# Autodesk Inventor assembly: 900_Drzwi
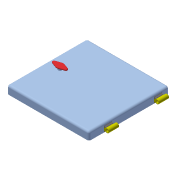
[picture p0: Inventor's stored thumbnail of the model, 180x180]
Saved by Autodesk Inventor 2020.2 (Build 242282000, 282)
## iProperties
Created: 2006-01
Part Number: 900_Drzwi
Document SubType Name: Weldment
Designer: F.Stasiak
Weld Material: Spawane aluminium-6061
Manager: www.cadconsulting.pl
Company: Fabian Stasiak CAD Consulting
Author: F.Stasiak
Subject: Zbiór ćwiczeń. Autodesk Inventor 2020. Kurs podstawowy
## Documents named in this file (5)
- C:\2020_Kurs_podstawowy\R7 Prezentacje\Komponenty\900_Drzwi.iam
- C:\2020_Kurs_podstawowy\R7 Prezentacje\Komponenty\900_Pokrywa.ipt
- C:\2020_Kurs_podstawowy\R7 Prezentacje\Komponenty\900_Zawias1.ipt
- C:\2020_Kurs_podstawowy\R7 Prezentacje\Komponenty\900_Rurka.ipt
- C:\2020_Kurs_podstawowy\R7 Prezentacje\Komponenty\900_Klamka.ipt
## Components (5 placed, 4 different names)
1. 900_Pokrywa:1 — Zestawiający:1, Zestawiający:2, Równoległy:1, Zestawiający:3, Równoległy:2, Zestawiający:5, Równoległy:3, Kąt:1
2. 900_Zawias1:1 — Zestawiający:1, Równoległy:1, Zestawiający:3, Zestawiający:4
3. 900_Zawias1:2 — Zestawiający:2, Zestawiający:4, Równoległy:2
4. 900_Rurka:1 — Zestawiający:5, Równoległy:3, Wstaw:1
5. 900_Klamka:1 — Wstaw:1, Kąt:1
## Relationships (10: Mate 5, Flush 3, Insert 1, Angle 1)
- Zestawiający:1 [Mate]: 900_Pokrywa:1 ↔ 900_Zawias1:1
- Zestawiający:2 [Mate]: 900_Pokrywa:1 ↔ 900_Zawias1:2
- Równoległy:1 [Flush]: 900_Pokrywa:1 ↔ 900_Zawias1:1
- Zestawiający:3 [Mate]: 900_Pokrywa:1 ↔ 900_Zawias1:1
- Zestawiający:4 [Mate]: 900_Zawias1:1 ↔ 900_Zawias1:2
- Równoległy:2 [Flush]: 900_Pokrywa:1 ↔ 900_Zawias1:2
- Zestawiający:5 [Mate]: 900_Pokrywa:1 ↔ 900_Rurka:1
- Równoległy:3 [Flush]: 900_Pokrywa:1 ↔ 900_Rurka:1
- Wstaw:1 [Insert]: 900_Rurka:1 ↔ 900_Klamka:1
- Kąt:1 [Angle]: 900_Pokrywa:1 ↔ 900_Klamka:1
